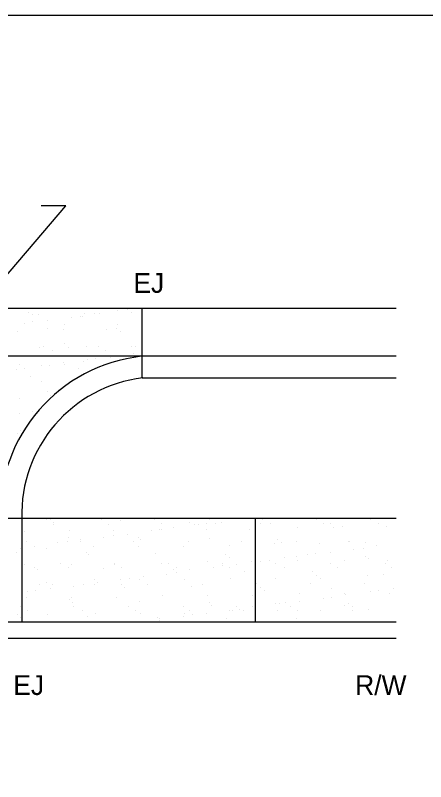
# Model space of a CAD drawing. Extents: x -118779 to -116979, y -104389 to -102939.
# Drawn here: x -118209.8 to -118085.1, y -103172.4 to -102939.3 of the extents above; entities that cross this region are included whole.
import ezdxf

# ---------------------------------------------------------------- set-up
doc = ezdxf.new("R2010")
doc.units = 0
for name, color, linetype in [('Default', 7, 'Continuous'), ('G-MARK', 7, 'Continuous'), ('Misc CnstDet(22)', 7, 'Continuous')]:
    doc.layers.add(name, color=color, linetype=linetype)

msp = doc.modelspace()

# ---------------------------------------------------------------- linework, layer by layer
at = {"layer": 'Default'}
msp.add_lwpolyline([(-118779.39, -102939.25), (-116979.39, -102939.25), (-116979.39, -104389.25), (-118779.39, -104389.25)], close=True, dxfattribs=at)
at = {"layer": 'G-MARK'}
msp.add_lwpolyline([(-118244.71, -103056.13), (-118194.52, -102997.23), (-118201.99, -102997.23)], dxfattribs=at)
at = {"layer": 'Misc CnstDet(22)'}
for p, q in [((-118205.72, -103029.58), (-118205.72, -103029.58)), ((-118188.72, -103030), (-118188.72, -103030)), ((-118185.81, -103030), (-118185.81, -103030)), ((-118184.15, -103030), (-118184.15, -103030)), ((-118178.76, -103029.17), (-118178.76, -103029.17)), ((-118175.86, -103028.75), (-118175.86, -103028.75)), ((-118175.86, -103028.75), (-118175.86, -103028.75)), ((-118174.61, -103029.58), (-118174.61, -103029.58)), ((-118171.71, -103028.34), (-118171.71, -103028.34)), ((-118171.3, -103049.49), (-118171.3, -103028.34)), ((-118204.48, -103030.41), (-118204.48, -103030.41)), ((-118204.48, -103032.48), (-118204.48, -103032.48)), ((-118202.82, -103030.41), (-118202.82, -103030.41)), ((-118199.92, -103032.07), (-118199.92, -103032.07)), ((-118192.86, -103031.24), (-118192.86, -103031.24)), ((-118189.96, -103030.83), (-118189.96, -103030.83)), ((-118189.55, -103030.83), (-118189.55, -103030.83)), ((-118206.97, -103032.9), (-118206.97, -103032.9)), ((-118199.92, -103034.56), (-118199.92, -103034.56)), ((-118194.94, -103033.31), (-118194.94, -103033.31)), ((-118179.18, -103034.56), (-118179.18, -103034.56)), ((-118178.76, -103033.31), (-118178.76, -103033.31)), ((-118209.04, -103035.39), (-118209.04, -103035.39)), ((-118195.35, -103034.97), (-118195.35, -103034.97)), ((-118182.08, -103034.97), (-118182.08, -103034.97)), ((-118177.93, -103035.39), (-118177.93, -103035.39)), ((-118194.94, -103039.12), (-118194.94, -103039.12)), ((-118202.4, -103040.37), (-118202.4, -103040.37)), ((-118201.16, -103039.95), (-118201.16, -103039.95)), ((-118198.67, -103041.19), (-118198.67, -103041.19)), ((-118193.69, -103040.37), (-118193.69, -103040.37)), ((-118188.3, -103039.95), (-118188.3, -103039.95)), ((-118184.57, -103039.95), (-118184.57, -103039.95)), ((-118182.5, -103041.19), (-118182.5, -103041.19)), ((-118174.61, -103039.95), (-118174.61, -103039.95)), ((-118173.37, -103039.95), (-118173.37, -103039.95)), ((-118187.89, -103044.1), (-118187.89, -103044.1)), ((-118185.4, -103043.68), (-118185.4, -103043.68)), ((-118180.84, -103043.27), (-118180.84, -103043.27)), ((-118173.79, -103042.02), (-118173.79, -103042.02)), ((-118208.63, -103045.34), (-118208.63, -103045.34)), ((-118201.99, -103045.76), (-118201.99, -103045.76)), ((-118199.5, -103045.76), (-118199.5, -103045.76)), ((-118195.35, -103044.93), (-118195.35, -103044.93)), ((-118194.94, -103045.34), (-118194.94, -103045.34)), ((-118189.13, -103044.51), (-118189.13, -103044.51)), ((-118209.45, -103047), (-118209.45, -103047)), ((-118206.97, -103046.59), (-118206.97, -103046.59)), ((-118190.79, -103046.59), (-118190.79, -103046.59)), ((-118205.31, -103049.08), (-118205.31, -103049.08)), ((-118201.99, -103050.73), (-118201.99, -103050.73)), ((-118196.6, -103053.22), (-118196.6, -103053.22)), ((-118208.63, -103055.71), (-118208.63, -103055.71)), ((-118199.92, -103053.64), (-118199.92, -103053.64)), ((-118199.09, -103054.88), (-118199.09, -103054.88)), ((-118208.63, -103060.27), (-118208.63, -103060.27)), ((-118204.48, -103059.86), (-118204.48, -103059.86)), ((-118209.04, -103066.5), (-118209.04, -103066.5)), ((-118208.21, -103065.67), (-118208.21, -103065.67)), ((-118207.8, -103123.73), (-118207.8, -103092.21)), ((-118200.33, -103092.63), (-118200.33, -103092.63)), ((-118199.09, -103092.63), (-118199.09, -103092.63)), ((-118183.74, -103092.63), (-118183.74, -103092.63)), ((-118177.93, -103093.04), (-118177.93, -103093.04)), ((-118167.56, -103092.63), (-118167.56, -103092.63)), ((-118150.97, -103092.63), (-118150.97, -103092.63)), ((-118136.87, -103123.73), (-118136.87, -103092.21)), ((-118134.8, -103092.63), (-118134.8, -103092.63)), ((-118118.21, -103092.63), (-118118.21, -103092.63)), ((-118102.03, -103092.63), (-118102.03, -103092.63)), ((-118198.26, -103093.46), (-118198.26, -103093.46)), ((-118198.26, -103094.28), (-118198.26, -103094.28)), ((-118181.67, -103094.28), (-118181.67, -103094.28)), ((-118165.9, -103095.53), (-118165.9, -103095.53)), ((-118165.49, -103093.87), (-118165.49, -103093.87)), ((-118165.49, -103095.53), (-118165.49, -103095.53)), ((-118161.76, -103095.11), (-118161.76, -103095.11)), ((-118156.78, -103093.46), (-118156.78, -103093.46)), ((-118155.54, -103094.28), (-118155.54, -103094.28)), ((-118154.29, -103094.28), (-118154.29, -103094.28)), ((-118151.8, -103093.87), (-118151.8, -103093.87)), ((-118151.8, -103095.53), (-118151.8, -103095.53)), ((-118148.9, -103093.87), (-118148.9, -103093.87)), ((-118147.24, -103093.46), (-118147.24, -103093.46)), ((-118138.53, -103095.53), (-118138.53, -103095.53)), ((-118135.21, -103093.87), (-118135.21, -103093.87)), ((-118132.31, -103093.87), (-118132.31, -103093.87)), ((-118124.01, -103095.11), (-118124.01, -103095.11)), ((-118116.13, -103093.87), (-118116.13, -103093.87)), ((-118114.06, -103093.87), (-118114.06, -103093.87)), ((-118113.23, -103095.11), (-118113.23, -103095.11)), ((-118110.33, -103094.7), (-118110.33, -103094.7)), ((-118099.54, -103093.87), (-118099.54, -103093.87)), ((-118097.05, -103094.7), (-118097.05, -103094.7)), ((-118206.97, -103096.36), (-118206.97, -103096.36)), ((-118193.28, -103095.94), (-118193.28, -103095.94)), ((-118180.01, -103095.94), (-118180.01, -103095.94)), ((-118180.01, -103097.6), (-118180.01, -103097.6)), ((-118175.86, -103097.19), (-118175.86, -103097.19)), ((-118168.39, -103095.94), (-118168.39, -103095.94)), ((-118206.55, -103099.26), (-118206.55, -103099.26)), ((-118197.01, -103099.68), (-118197.01, -103099.68)), ((-118194.11, -103099.26), (-118194.11, -103099.26)), ((-118193.69, -103098.02), (-118193.69, -103098.02)), ((-118189.96, -103098.85), (-118189.96, -103098.85)), ((-118189.96, -103099.26), (-118189.96, -103099.26)), ((-118182.91, -103098.02), (-118182.91, -103098.02)), ((-118173.79, -103099.26), (-118173.79, -103099.26)), ((-118172.54, -103098.02), (-118172.54, -103098.02)), ((-118171.71, -103098.85), (-118171.71, -103098.85)), ((-118157.19, -103099.26), (-118157.19, -103099.26)), ((-118150.97, -103098.43), (-118150.97, -103098.43)), ((-118141.02, -103099.26), (-118141.02, -103099.26)), ((-118131.06, -103100.09), (-118131.06, -103100.09)), ((-118130.23, -103098.85), (-118130.23, -103098.85)), ((-118128.99, -103099.68), (-118128.99, -103099.68)), ((-118124.43, -103099.26), (-118124.43, -103099.26)), ((-118117.38, -103100.09), (-118117.38, -103100.09)), ((-118108.67, -103099.26), (-118108.67, -103099.26)), ((-118108.25, -103099.26), (-118108.25, -103099.26)), ((-118103.28, -103099.68), (-118103.28, -103099.68)), ((-118208.21, -103101.34), (-118208.21, -103101.34)), ((-118204.06, -103100.92), (-118204.06, -103100.92)), ((-118200.33, -103101.34), (-118200.33, -103101.34)), ((-118186.23, -103100.92), (-118186.23, -103100.92)), ((-118172.54, -103100.92), (-118172.54, -103100.92)), ((-118158.85, -103100.92), (-118158.85, -103100.92)), ((-118144.75, -103100.51), (-118144.75, -103100.51)), ((-118107.01, -103101.75), (-118107.01, -103101.75)), ((-118104.1, -103101.34), (-118104.1, -103101.34)), ((-118099.96, -103100.51), (-118099.96, -103100.51)), ((-118209.45, -103102.58), (-118209.45, -103102.58)), ((-118188.3, -103102.58), (-118188.3, -103102.58)), ((-118187.47, -103103.41), (-118187.47, -103103.41)), ((-118167.15, -103102.99), (-118167.15, -103102.99)), ((-118146, -103103.41), (-118146, -103103.41)), ((-118144.75, -103104.24), (-118144.75, -103104.24)), ((-118128.16, -103104.24), (-118128.16, -103104.24)), ((-118124.43, -103103.82), (-118124.43, -103103.82)), ((-118121.11, -103103.41), (-118121.11, -103103.41)), ((-118118.62, -103102.99), (-118118.62, -103102.99)), ((-118114.06, -103102.58), (-118114.06, -103102.58)), ((-118103.28, -103103.82), (-118103.28, -103103.82)), ((-118102.45, -103104.65), (-118102.45, -103104.65)), ((-118206.97, -103106.31), (-118206.97, -103106.31)), ((-118204.06, -103107.14), (-118204.06, -103107.14)), ((-118196.18, -103105.9), (-118196.18, -103105.9)), ((-118193.69, -103107.14), (-118193.69, -103107.14)), ((-118192.86, -103106.31), (-118192.86, -103106.31)), ((-118179.59, -103105.9), (-118179.59, -103105.9)), ((-118179.59, -103106.31), (-118179.59, -103106.31)), ((-118177.52, -103107.14), (-118177.52, -103107.14)), ((-118165.49, -103105.9), (-118165.49, -103105.9)), ((-118163.42, -103105.9), (-118163.42, -103105.9)), ((-118160.93, -103107.14), (-118160.93, -103107.14)), ((-118151.39, -103105.48), (-118151.39, -103105.48)), ((-118149.73, -103107.14), (-118149.73, -103107.14)), ((-118146.83, -103105.9), (-118146.83, -103105.9)), ((-118146.83, -103106.73), (-118146.83, -103106.73)), ((-118144.75, -103107.14), (-118144.75, -103107.14)), ((-118142.68, -103106.31), (-118142.68, -103106.31)), ((-118138.12, -103105.48), (-118138.12, -103105.48)), ((-118135.21, -103105.48), (-118135.21, -103105.48)), ((-118132.72, -103105.07), (-118132.72, -103105.07)), ((-118130.65, -103105.9), (-118130.65, -103105.9)), ((-118128.16, -103107.14), (-118128.16, -103107.14)), ((-118124.01, -103105.07), (-118124.01, -103105.07)), ((-118114.06, -103105.9), (-118114.06, -103105.9)), ((-118111.99, -103107.14), (-118111.99, -103107.14)), ((-118109.91, -103105.07), (-118109.91, -103105.07)), ((-118097.47, -103105.9), (-118097.47, -103105.9)), ((-118096.64, -103105.07), (-118096.64, -103105.07)), ((-118095.39, -103107.14), (-118095.39, -103107.14)), ((-118203.23, -103107.97), (-118203.23, -103107.97)), ((-118182.91, -103107.56), (-118182.91, -103107.56)), ((-118163.83, -103109.22), (-118163.83, -103109.22)), ((-118161.76, -103107.97), (-118161.76, -103107.97)), ((-118160.93, -103108.8), (-118160.93, -103108.8)), ((-118160.93, -103108.8), (-118160.93, -103108.8)), ((-118156.78, -103107.97), (-118156.78, -103107.97)), ((-118140.19, -103108.39), (-118140.19, -103108.39)), ((-118119.45, -103108.39), (-118119.45, -103108.39)), ((-118097.88, -103109.22), (-118097.88, -103109.22)), ((-118200.33, -103111.7), (-118200.33, -103111.7)), ((-118185.81, -103110.88), (-118185.81, -103110.88)), ((-118184.98, -103111.7), (-118184.98, -103111.7)), ((-118177.93, -103110.88), (-118177.93, -103110.88)), ((-118175.03, -103110.46), (-118175.03, -103110.46)), ((-118172.13, -103110.88), (-118172.13, -103110.88)), ((-118170.88, -103110.05), (-118170.88, -103110.05)), ((-118158.44, -103110.88), (-118158.44, -103110.88)), ((-118144.34, -103110.46), (-118144.34, -103110.46)), ((-118130.65, -103110.46), (-118130.65, -103110.46)), ((-118118.21, -103109.63), (-118118.21, -103109.63)), ((-118116.96, -103110.46), (-118116.96, -103110.46)), ((-118102.86, -103109.63), (-118102.86, -103109.63)), ((-118203.65, -103114.19), (-118203.65, -103114.19)), ((-118202.4, -103112.53), (-118202.4, -103112.53)), ((-118199.09, -103113.78), (-118199.09, -103113.78)), ((-118198.67, -103112.53), (-118198.67, -103112.53)), ((-118192.03, -103112.95), (-118192.03, -103112.95)), ((-118189.13, -103112.53), (-118189.13, -103112.53)), ((-118185.81, -103112.53), (-118185.81, -103112.53)), ((-118177.52, -103112.53), (-118177.52, -103112.53)), ((-118176.69, -103113.36), (-118176.69, -103113.36)), ((-118169.64, -103112.53), (-118169.64, -103112.53)), ((-118156.37, -103112.95), (-118156.37, -103112.95)), ((-118153.05, -103112.53), (-118153.05, -103112.53)), ((-118136.46, -103112.12), (-118136.46, -103112.12)), ((-118135.21, -103113.36), (-118135.21, -103113.36)), ((-118133.97, -103114.19), (-118133.97, -103114.19)), ((-118120.28, -103112.12), (-118120.28, -103112.12)), ((-118113.64, -103113.78), (-118113.64, -103113.78)), ((-118103.69, -103112.12), (-118103.69, -103112.12)), ((-118099.54, -103114.19), (-118099.54, -103114.19)), ((-118094.98, -103113.78), (-118094.98, -103113.78)), ((-118206.55, -103116.27), (-118206.55, -103116.27)), ((-118206.14, -103114.61), (-118206.14, -103114.61)), ((-118192.86, -103116.27), (-118192.86, -103116.27)), ((-118179.18, -103116.27), (-118179.18, -103116.27)), ((-118165.08, -103115.85), (-118165.08, -103115.85)), ((-118151.39, -103115.85), (-118151.39, -103115.85)), ((-118137.7, -103115.85), (-118137.7, -103115.85)), ((-118123.6, -103115.02), (-118123.6, -103115.02)), ((-118113.64, -103116.27), (-118113.64, -103116.27)), ((-118109.91, -103115.02), (-118109.91, -103115.02)), ((-118109.5, -103115.44), (-118109.5, -103115.44)), ((-118102.03, -103114.61), (-118102.03, -103114.61)), ((-118096.22, -103115.02), (-118096.22, -103115.02)), ((-118193.28, -103117.1), (-118193.28, -103117.1)), ((-118192.45, -103117.93), (-118192.45, -103117.93)), ((-118172.13, -103117.51), (-118172.13, -103117.51)), ((-118150.97, -103117.93), (-118150.97, -103117.93)), ((-118150.14, -103118.76), (-118150.14, -103118.76)), ((-118130.65, -103118.34), (-118130.65, -103118.34)), ((-118129.41, -103118.34), (-118129.41, -103118.34)), ((-118127.75, -103117.93), (-118127.75, -103117.93)), ((-118123.6, -103117.51), (-118123.6, -103117.51)), ((-118116.13, -103116.68), (-118116.13, -103116.68)), ((-118109.91, -103118.76), (-118109.91, -103118.76)), ((-118108.67, -103118.34), (-118108.67, -103118.34)), ((-118208.21, -103119.17), (-118208.21, -103119.17)), ((-118206.14, -103120.41), (-118206.14, -103120.41)), ((-118192.03, -103119.17), (-118192.03, -103119.17)), ((-118189.55, -103120.41), (-118189.55, -103120.41)), ((-118175.44, -103119.17), (-118175.44, -103119.17)), ((-118173.37, -103120.41), (-118173.37, -103120.41)), ((-118158.85, -103119.17), (-118158.85, -103119.17)), ((-118156.78, -103120.41), (-118156.78, -103120.41)), ((-118144.75, -103120.41), (-118144.75, -103120.41)), ((-118143.92, -103120.41), (-118143.92, -103120.41)), ((-118142.68, -103119.17), (-118142.68, -103119.17)), ((-118141.85, -103120), (-118141.85, -103120)), ((-118140.6, -103120.41), (-118140.6, -103120.41)), ((-118137.7, -103119.17), (-118137.7, -103119.17)), ((-118130.23, -103120.41), (-118130.23, -103120.41)), ((-118126.09, -103119.17), (-118126.09, -103119.17)), ((-118124.01, -103120.41), (-118124.01, -103120.41)), ((-118116.96, -103120.41), (-118116.96, -103120.41)), ((-118107.42, -103119.17), (-118107.42, -103119.17)), ((-118107.42, -103120.41), (-118107.42, -103120.41)), ((-118102.45, -103120), (-118102.45, -103120)), ((-118209.04, -103121.66), (-118209.04, -103121.66)), ((-118208.21, -103122.49), (-118208.21, -103122.49)), ((-118199.92, -103121.66), (-118199.92, -103121.66)), ((-118187.89, -103122.07), (-118187.89, -103122.07)), ((-118185.4, -103121.24), (-118185.4, -103121.24)), ((-118171.71, -103121.24), (-118171.71, -103121.24)), ((-118166.73, -103122.49), (-118166.73, -103122.49)), ((-118165.9, -103122.9), (-118165.9, -103122.9)), ((-118165.9, -103123.32), (-118165.9, -103123.32)), ((-118158.85, -103122.07), (-118158.85, -103122.07)), ((-118158.44, -103121.24), (-118158.44, -103121.24)), ((-118155.95, -103121.66), (-118155.95, -103121.66)), ((-118151.8, -103121.24), (-118151.8, -103121.24)), ((-118145.58, -103122.9), (-118145.58, -103122.9)), ((-118124.43, -103122.9), (-118124.43, -103122.9)), ((-118170.47, -103123.73), (-118170.47, -103123.73)), ((-118102.86, -103123.73), (-118102.86, -103123.73))]:
    msp.add_line(p, q, dxfattribs=at)
for points in [[(-118415.18, -103028.34), (-118094.15, -103028.34)], [(-118410.62, -103042.85), (-118094.15, -103042.85)], [(-118171.3, -103049.49), (-118094.15, -103049.49)], [(-118396.1, -103092.21), (-118094.15, -103092.21)], [(-118386.97, -103123.73), (-118094.15, -103123.73)], [(-118385.73, -103128.71), (-118094.15, -103128.71)]]:
    msp.add_lwpolyline(points, dxfattribs=at)
for radius, start, end in [(48.29, 96.2941, 181.6386), (41.71, 96.7732, 181.8974)]:
    msp.add_arc((-118166.18, -103090.99), radius, start, end, dxfattribs=at)

# ---------------------------------------------------------------- texts
for s, p in [('EJ', (-118173.96, -103023.68)), ('R/W', (-118106.56, -103146.03)), ('EJ', (-118210.45, -103146.03))]:
    msp.add_text(s, height=6, dxfattribs=at).set_placement(p)

doc.saveas('drawing.dxf')
